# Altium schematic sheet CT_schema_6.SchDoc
size 287 x 160 mm
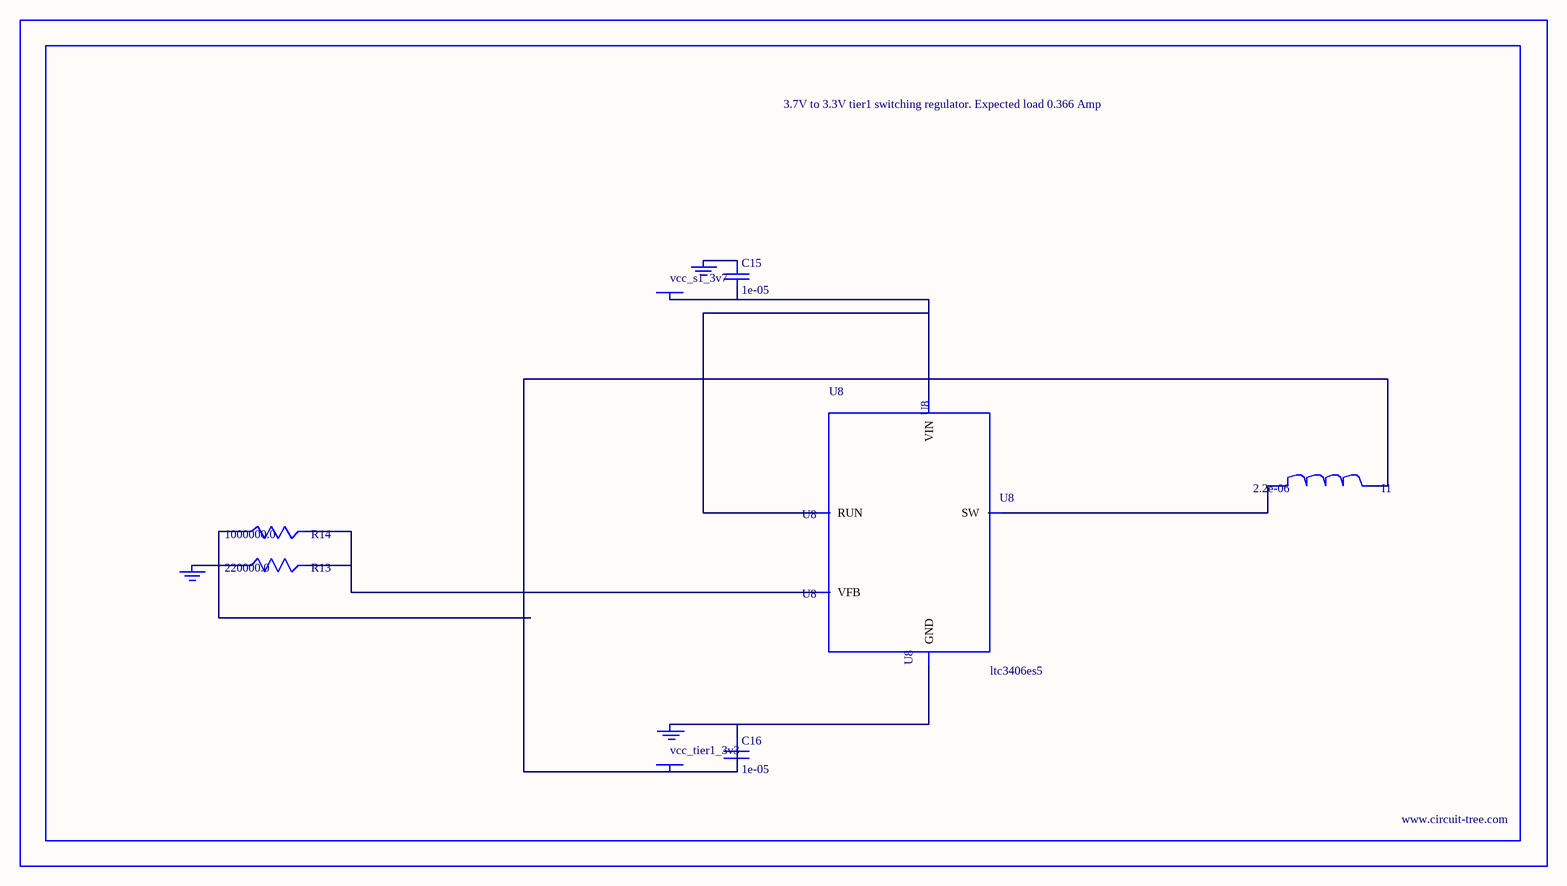
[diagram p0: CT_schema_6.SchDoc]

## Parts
BORDER5  (no value)
C15  1e-05  [C0805]
C16  1e-05  [C0805]
GND_INSTANCE_5_0  (no value)
GND_INSTANCE_5_1  (no value)
GND_INSTANCE_5_2  (no value)
I1  2.2e-06  [L0805]
POWER_INSTANCE_5_0  vcc_tier1_3v3
POWER_INSTANCE_5_1  vcc_s1_3v7
R13  220000.0  [R0603]
R14  1000000.0  [R0603]
U8  ltc3406es5  [TSOT-23-5]

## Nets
NetC15_1: C15.1 GND_INSTANCE_5_1.0(GND)
NetC15_2: C15.2 POWER_INSTANCE_5_1.0(PWR) U8.1(RUN) U8.4(VIN)
NetC16_1: C16.1 GND_INSTANCE_5_0.0(GND) U8.2(GND)
NetC16_2: C16.2 I1.2 POWER_INSTANCE_5_0.0(PWR) R14.1
NetGND_INSTANCE_5_2_0: GND_INSTANCE_5_2.0(GND) R13.1
NetI1_1: I1.1 U8.3(SW)
NetR13_2: R13.2 R14.2 U8.5(VFB)

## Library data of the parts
BORDER5 = BORDER_PAGE5
C15 C16 = C0805C106K8RACTU
GND_INSTANCE_5_0-GND_INSTANCE_5_2 = GND
I1 = L0805C2R2MDWIT
POWER_INSTANCE_5_0 POWER_INSTANCE_5_1 = PWR
R13 = RC0603JR-07220KL
R14 = RC0603JR-071ML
